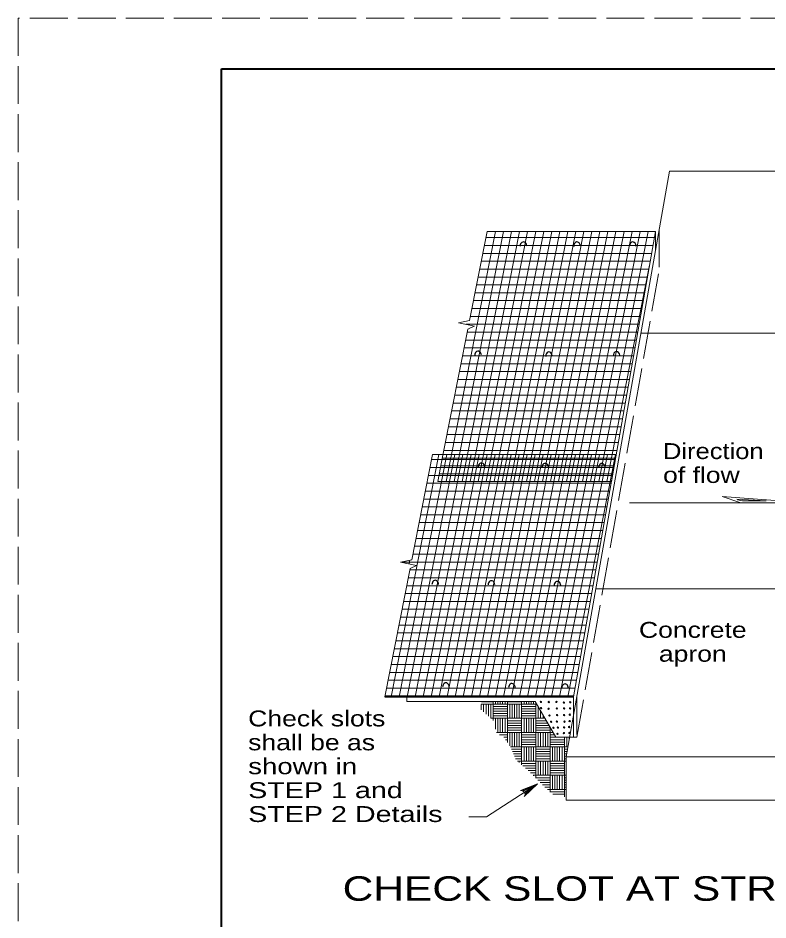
# Model space of a CAD drawing. Extents: x 1083.1 to 1117.1, y 719.4 to 741.4.
# Drawn here: x 1083.13 to 1090.49, y 732.5 to 741.35 of the extents above; entities that cross this region are included whole.
import ezdxf
from ezdxf.enums import TextEntityAlignment as Align

# ---------------------------------------------------------------- set-up
doc = ezdxf.new("R2010")
doc.units = 0
doc.header["$LTSCALE"] = 0.062
doc.linetypes.add('LONG_DASHED', pattern=[7.5, 6, -1.5])
doc.layers.add('1', color=7, linetype='Continuous', lineweight=13)

msp = doc.modelspace()

# ---------------------------------------------------------------- linework, layer by layer
at = {"layer": '1', "lineweight": 25}
msp.add_line((1085.12642, 740.85408), (1116.62642, 740.85408), dxfattribs=at)
at = {"layer": '1'}
for p, q in [((1088.51183, 734.09967), (1089.52617, 739.8515)), ((1093.0215, 739.8515), (1089.52617, 739.8515)), ((1087.33167, 736.80383), (1087.81692, 739.259)), ((1087.41058, 736.80383), (1087.89583, 739.259)), ((1087.48942, 736.80383), (1087.97467, 739.259)), ((1087.56825, 736.80383), (1088.0535, 739.259)), ((1087.64708, 736.80383), (1088.13242, 739.259)), ((1087.72342, 739.19792), (1089.37667, 739.19792)), ((1087.726, 736.80383), (1088.21125, 739.259)), ((1087.7355, 739.259), (1089.38733, 739.259)), ((1087.80483, 736.80383), (1088.29017, 739.259)), ((1087.88375, 736.80383), (1088.369, 739.259)), ((1087.96267, 736.80383), (1088.44792, 739.259)), ((1088.0415, 736.80383), (1088.52675, 739.259)), ((1088.12042, 736.80383), (1088.60567, 739.259)), ((1088.19925, 736.80383), (1088.6845, 739.259)), ((1088.27817, 736.80383), (1088.76342, 739.259)), ((1088.357, 736.80383), (1088.84233, 739.259)), ((1088.43592, 736.80383), (1088.92117, 739.259)), ((1088.51475, 736.80383), (1089.00008, 739.259)), ((1088.59367, 736.80383), (1089.07892, 739.259)), ((1088.67258, 736.80383), (1089.15783, 739.259)), ((1088.75142, 736.80383), (1089.23667, 739.259)), ((1088.83033, 736.80383), (1089.31558, 739.259)), ((1089.38733, 739.259), (1088.9545, 736.80383)), ((1089.38733, 739.259), (1089.38733, 739.06475)), ((1087.70817, 739.1205), (1089.363, 739.1205)), ((1087.69283, 739.04317), (1089.34933, 739.04317)), ((1087.6775, 738.96583), (1089.33567, 738.96583)), ((1088.90917, 736.80383), (1089.32892, 738.92725)), ((1087.66225, 738.88842), (1089.32208, 738.88842)), ((1087.63158, 738.73367), (1089.29475, 738.73367)), ((1087.64692, 738.81108), (1089.30842, 738.81108)), ((1087.61633, 738.65633), (1089.28108, 738.65633)), ((1087.60108, 738.57892), (1089.26742, 738.57892)), ((1087.58583, 738.50158), (1089.25383, 738.50158)), ((1087.5705, 738.42417), (1089.24017, 738.42417)), ((1087.30092, 737.06058), (1087.54575, 738.29875)), ((1087.52417, 738.34683), (1089.2265, 738.34683)), ((1087.54575, 738.29875), (1087.60658, 738.32825)), ((1087.53992, 738.26942), (1089.21283, 738.26942)), ((1092.74075, 738.25933), (1089.24533, 738.25933)), ((1087.50933, 738.11467), (1089.18567, 738.11467)), ((1087.52458, 738.19208), (1089.19933, 738.19208)), ((1087.494, 738.03733), (1089.172, 738.03733)), ((1087.47867, 737.95992), (1089.15833, 737.95992)), ((1087.46342, 737.88258), (1089.14467, 737.88258)), ((1087.44808, 737.80525), (1089.13108, 737.80525)), ((1087.43275, 737.72783), (1089.11742, 737.72783)), ((1087.41758, 737.6505), (1089.10375, 737.6505)), ((1087.387, 737.49575), (1089.07642, 737.49575)), ((1087.40225, 737.57308), (1089.09008, 737.57308)), ((1087.37167, 737.41833), (1089.06283, 737.41833)), ((1087.35633, 737.341), (1089.04917, 737.341)), ((1087.34108, 737.26358), (1089.0355, 737.26358)), ((1087.32575, 737.18625), (1089.02192, 737.18625)), ((1086.7905, 734.6895), (1087.26042, 737.06717)), ((1086.86942, 734.6895), (1087.33933, 737.06717)), ((1086.94825, 734.6895), (1087.41825, 737.06717)), ((1087.02717, 734.6895), (1087.49708, 737.06717)), ((1087.106, 734.6895), (1087.576, 737.06717)), ((1087.18492, 734.6895), (1087.65483, 737.06717)), ((1087.25025, 736.80383), (1087.30092, 737.06058)), ((1087.26375, 734.6895), (1087.73375, 737.06717)), ((1087.3105, 737.10883), (1089.00825, 737.10883)), ((1087.34267, 734.6895), (1087.81258, 737.06717)), ((1087.42158, 734.6895), (1087.8915, 737.06717)), ((1087.50042, 734.6895), (1087.97033, 737.06717)), ((1087.57933, 734.6895), (1088.04925, 737.06717)), ((1087.65817, 734.6895), (1088.12817, 737.06717)), ((1087.73708, 734.6895), (1088.207, 737.06717)), ((1087.81592, 734.6895), (1088.28592, 737.06717)), ((1087.89483, 734.6895), (1088.36475, 737.06717)), ((1087.97367, 734.6895), (1088.44367, 737.06717)), ((1088.05258, 734.6895), (1088.5225, 737.06717)), ((1088.1315, 734.6895), (1088.60142, 737.06717)), ((1088.21033, 734.6895), (1088.68025, 737.06717)), ((1088.28925, 734.6895), (1088.75917, 737.06717)), ((1088.36808, 734.6895), (1088.83808, 737.06717)), ((1088.44692, 734.6895), (1088.91692, 737.06717)), ((1088.52575, 734.6895), (1088.99583, 737.06717)), ((1089.00092, 737.06717), (1088.58167, 734.6895)), ((1087.18892, 737.018), (1088.99225, 737.018)), ((1087.29517, 737.0315), (1088.99467, 737.0315)), ((1087.17367, 736.94067), (1088.97858, 736.94067)), ((1087.26517, 736.87975), (1088.96467, 736.87975)), ((1087.28017, 736.95558), (1088.97967, 736.95558)), ((1087.143, 736.78592), (1088.95133, 736.78592)), ((1087.15833, 736.86325), (1088.96492, 736.86325)), ((1087.25025, 736.80383), (1088.9545, 736.80383)), ((1087.12775, 736.7085), (1088.93767, 736.7085)), ((1087.11242, 736.63117), (1088.924, 736.63117)), ((1087.09717, 736.55375), (1088.91033, 736.55375)), ((1087.08183, 736.47642), (1088.89675, 736.47642)), ((1087.06658, 736.399), (1088.88308, 736.399)), ((1087.05133, 736.32167), (1088.86942, 736.32167)), ((1087.02067, 736.16692), (1088.84217, 736.16692)), ((1087.036, 736.24425), (1088.85575, 736.24425)), ((1087.00542, 736.0895), (1088.82858, 736.0895)), ((1086.888, 736.01217), (1088.81492, 736.01217)), ((1086.89367, 736.00942), (1086.8945, 736.0135)), ((1086.96925, 735.99292), (1086.97675, 736.03075)), ((1086.72858, 734.6895), (1086.97733, 735.94775)), ((1086.97475, 735.93475), (1088.80125, 735.93475)), ((1086.9595, 735.85742), (1088.78758, 735.85742)), ((1086.94417, 735.78008), (1088.77392, 735.78008)), ((1092.29817, 735.74967), (1088.80283, 735.74967)), ((1086.92883, 735.70267), (1088.76033, 735.70267)), ((1086.89833, 735.54792), (1088.733, 735.54792)), ((1086.91358, 735.62533), (1088.74667, 735.62533)), ((1086.88308, 735.47058), (1088.71933, 735.47058)), ((1086.86775, 735.39317), (1088.70575, 735.39317)), ((1086.85242, 735.31583), (1088.69208, 735.31583)), ((1086.83717, 735.23842), (1088.67842, 735.23842)), ((1086.82183, 735.16108), (1088.66483, 735.16108)), ((1086.8065, 735.08367), (1088.65117, 735.08367)), ((1086.77592, 734.92892), (1088.62392, 734.92892)), ((1086.79125, 735.00633), (1088.63758, 735.00633)), ((1086.76067, 734.85158), (1088.61025, 734.85158)), ((1086.74533, 734.77425), (1088.59658, 734.77425)), ((1086.73, 734.69683), (1088.583, 734.69683)), ((1086.94475, 734.6895), (1086.94475, 734.64275)), ((1088.58167, 734.6895), (1088.58167, 734.4955)), ((1088.20683, 734.64275), (1086.94475, 734.64275)), ((1087.67692, 734.56183), (1087.67692, 734.61242)), ((1088.22142, 734.61758), (1087.67742, 734.61758)), ((1087.7935, 734.64083), (1087.67975, 734.64083)), ((1087.70025, 734.54758), (1087.70025, 734.61758)), ((1087.72358, 734.54758), (1087.72358, 734.61758)), ((1087.74692, 734.54758), (1087.74692, 734.61758)), ((1087.77025, 734.54758), (1087.77025, 734.61758)), ((1087.7935, 734.45683), (1087.7935, 734.64275)), ((1087.8635, 734.59425), (1087.7935, 734.59425)), ((1087.8635, 734.57092), (1087.7935, 734.57092)), ((1087.81683, 734.61758), (1087.81683, 734.64275)), ((1087.84017, 734.61758), (1087.84017, 734.64275)), ((1087.8635, 734.61758), (1087.8635, 734.64275)), ((1087.9335, 734.59425), (1087.8635, 734.59425)), ((1087.9335, 734.57092), (1087.8635, 734.57092)), ((1087.88683, 734.61758), (1087.88683, 734.64275)), ((1087.91017, 734.61758), (1087.91017, 734.64275)), ((1087.9335, 734.24017), (1087.9335, 734.64275)), ((1088.07342, 734.64083), (1087.9335, 734.64083)), ((1087.95683, 734.54758), (1087.95683, 734.61758)), ((1087.98008, 734.54758), (1087.98008, 734.61758)), ((1088.00342, 734.54758), (1088.00342, 734.61758)), ((1088.02675, 734.54758), (1088.02675, 734.61758)), ((1088.05008, 734.54758), (1088.05008, 734.61758)), ((1088.07342, 734.02175), (1088.07342, 734.64275)), ((1088.14342, 734.59425), (1088.07342, 734.59425)), ((1088.14342, 734.57092), (1088.07342, 734.57092)), ((1088.09675, 734.61758), (1088.09675, 734.64275)), ((1088.12008, 734.61758), (1088.12008, 734.64275)), ((1088.14342, 734.61758), (1088.14342, 734.64275)), ((1088.21333, 734.59425), (1088.14342, 734.59425)), ((1088.21333, 734.57092), (1088.14342, 734.57092)), ((1088.16667, 734.61758), (1088.16667, 734.64275)), ((1088.19, 734.61758), (1088.19, 734.64275)), ((1088.40858, 734.29375), (1088.20683, 734.64275)), ((1088.21333, 733.89075), (1088.21333, 734.63158)), ((1088.23667, 734.54758), (1088.23667, 734.59125)), ((1087.70025, 734.54083), (1087.70025, 734.54758)), ((1087.72358, 734.51983), (1087.72358, 734.54758)), ((1087.74692, 734.49883), (1087.74692, 734.54758)), ((1087.77025, 734.47783), (1087.77025, 734.54758)), ((1088.30233, 734.47767), (1087.7705, 734.47767)), ((1087.8635, 734.54758), (1087.7935, 734.54758)), ((1087.8635, 734.52425), (1087.7935, 734.52425)), ((1087.8635, 734.50092), (1087.7935, 734.50092)), ((1087.81683, 734.37233), (1087.81683, 734.47767)), ((1087.84017, 734.33775), (1087.84017, 734.47767)), ((1087.9335, 734.54758), (1087.8635, 734.54758)), ((1087.9335, 734.52425), (1087.8635, 734.52425)), ((1087.9335, 734.50092), (1087.8635, 734.50092)), ((1087.8635, 734.33775), (1087.8635, 734.47767)), ((1087.88683, 734.33775), (1087.88683, 734.47767)), ((1087.91017, 734.33775), (1087.91017, 734.47767)), ((1087.95683, 734.47767), (1087.95683, 734.54758)), ((1087.98008, 734.47767), (1087.98008, 734.54758)), ((1088.00342, 734.47767), (1088.00342, 734.54758)), ((1088.02675, 734.47767), (1088.02675, 734.54758)), ((1088.05008, 734.47767), (1088.05008, 734.54758)), ((1088.14342, 734.54758), (1088.07342, 734.54758)), ((1088.14342, 734.52425), (1088.07342, 734.52425)), ((1088.14342, 734.50092), (1088.07342, 734.50092)), ((1088.09675, 734.33775), (1088.09675, 734.47767)), ((1088.12008, 734.33775), (1088.12008, 734.47767)), ((1088.21333, 734.54758), (1088.14342, 734.54758)), ((1088.21333, 734.52425), (1088.14342, 734.52425)), ((1088.21333, 734.50092), (1088.14342, 734.50092)), ((1088.14342, 734.33775), (1088.14342, 734.47767)), ((1088.16667, 734.33775), (1088.16667, 734.47767)), ((1088.19, 734.33775), (1088.19, 734.47767)), ((1088.23667, 734.47767), (1088.23667, 734.54758)), ((1088.26, 734.47767), (1088.26, 734.55083)), ((1088.26, 734.54758), (1088.26, 734.55083)), ((1088.28333, 734.47767), (1088.28333, 734.5105)), ((1088.07342, 734.45433), (1087.9335, 734.45433)), ((1088.07342, 734.431), (1087.9335, 734.431)), ((1088.07342, 734.40767), (1087.9335, 734.40767)), ((1088.31583, 734.45433), (1088.21333, 734.45433)), ((1088.32925, 734.431), (1088.21333, 734.431)), ((1088.34267, 734.40767), (1088.21333, 734.40767)), ((1088.35325, 733.75117), (1088.35325, 734.38942)), ((1088.38317, 734.33775), (1087.82483, 734.33775)), ((1087.8635, 734.31442), (1087.85642, 734.31442)), ((1087.9335, 734.31442), (1087.8635, 734.31442)), ((1088.07342, 734.38433), (1087.9335, 734.38433)), ((1088.07342, 734.361), (1087.9335, 734.361)), ((1087.95683, 734.26775), (1087.95683, 734.33775)), ((1087.98008, 734.26775), (1087.98008, 734.33775)), ((1088.00342, 734.26775), (1088.00342, 734.33775)), ((1088.02675, 734.26775), (1088.02675, 734.33775)), ((1088.05008, 734.26775), (1088.05008, 734.33775)), ((1088.14342, 734.31442), (1088.07342, 734.31442)), ((1088.21333, 734.31442), (1088.14342, 734.31442)), ((1088.35325, 734.38433), (1088.21333, 734.38433)), ((1088.35325, 734.361), (1088.21333, 734.361)), ((1088.23667, 734.26775), (1088.23667, 734.33775)), ((1088.26, 734.26775), (1088.26, 734.33775)), ((1088.28333, 734.26775), (1088.28333, 734.33775)), ((1088.30667, 734.26775), (1088.30667, 734.33775)), ((1088.32992, 734.26775), (1088.32992, 734.33775)), ((1088.39667, 734.31442), (1088.35325, 734.31442)), ((1088.37658, 734.33775), (1088.37658, 734.349)), ((1087.9335, 734.29108), (1087.89842, 734.29108)), ((1087.9335, 734.26775), (1087.9145, 734.26775)), ((1087.9335, 734.24442), (1087.93058, 734.24442)), ((1087.95683, 734.20625), (1087.95683, 734.26775)), ((1087.98008, 734.19775), (1087.98008, 734.26775)), ((1088.00342, 734.19775), (1088.00342, 734.26775)), ((1088.02675, 734.19775), (1088.02675, 734.26775)), ((1088.05008, 734.19775), (1088.05008, 734.26775)), ((1088.14342, 734.29108), (1088.07342, 734.29108)), ((1088.14342, 734.26775), (1088.07342, 734.26775)), ((1088.14342, 734.24442), (1088.07342, 734.24442)), ((1088.14342, 734.22108), (1088.07342, 734.22108)), ((1088.21333, 734.29108), (1088.14342, 734.29108)), ((1088.21333, 734.26775), (1088.14342, 734.26775)), ((1088.21333, 734.24442), (1088.14342, 734.24442)), ((1088.21333, 734.22108), (1088.14342, 734.22108)), ((1088.23667, 734.19775), (1088.23667, 734.26775)), ((1088.26, 734.19775), (1088.26, 734.26775)), ((1088.28333, 734.19775), (1088.28333, 734.26775)), ((1088.30667, 734.19775), (1088.30667, 734.26775)), ((1088.32992, 734.19775), (1088.32992, 734.26775)), ((1088.42325, 734.29108), (1088.35325, 734.29108)), ((1088.42325, 734.26775), (1088.35325, 734.26775)), ((1088.42325, 734.24442), (1088.35325, 734.24442)), ((1088.42325, 734.22108), (1088.35325, 734.22108)), ((1088.40858, 734.29375), (1088.54608, 734.29375)), ((1088.49325, 734.29108), (1088.42325, 734.29108)), ((1088.49325, 734.26775), (1088.42325, 734.26775)), ((1088.49325, 734.24442), (1088.42325, 734.24442)), ((1088.49325, 734.22108), (1088.42325, 734.22108)), ((1088.49325, 733.70808), (1088.49325, 734.29375)), ((1088.5165, 734.26775), (1088.5165, 734.29375)), ((1088.5165, 734.19775), (1088.5165, 734.26775)), ((1088.53983, 734.25842), (1088.53983, 734.29375)), ((1088.52917, 734.19775), (1087.96267, 734.19775)), ((1088.07342, 734.1745), (1087.973, 734.1745)), ((1088.07342, 734.15117), (1087.98333, 734.15117)), ((1088.07342, 734.12783), (1087.99367, 734.12783)), ((1088.09675, 734.05783), (1088.09675, 734.19775)), ((1088.12008, 734.05783), (1088.12008, 734.19775)), ((1088.14342, 734.05783), (1088.14342, 734.19775)), ((1088.16667, 734.05783), (1088.16667, 734.19775)), ((1088.19, 734.05783), (1088.19, 734.19775)), ((1088.35325, 734.1745), (1088.21333, 734.1745)), ((1088.35325, 734.15117), (1088.21333, 734.15117)), ((1088.35325, 734.12783), (1088.21333, 734.12783)), ((1088.37658, 734.05783), (1088.37658, 734.19775)), ((1088.39992, 734.05783), (1088.39992, 734.19775)), ((1088.42325, 734.05783), (1088.42325, 734.19775)), ((1088.44658, 734.05783), (1088.44658, 734.19775)), ((1088.46992, 734.05783), (1088.46992, 734.19775)), ((1088.525, 734.1745), (1088.49325, 734.1745)), ((1088.52092, 734.15117), (1088.49325, 734.15117)), ((1088.51683, 734.12783), (1088.49325, 734.12783)), ((1088.07342, 734.1045), (1088.004, 734.1045)), ((1088.07342, 734.08117), (1088.01433, 734.08117)), ((1088.51183, 734.05783), (1088.03375, 734.05783)), ((1088.05008, 734.043), (1088.05008, 734.05783)), ((1088.14342, 734.03458), (1088.07342, 734.03458)), ((1088.21333, 734.03458), (1088.14342, 734.03458)), ((1088.35325, 734.1045), (1088.21333, 734.1045)), ((1088.35325, 734.08117), (1088.21333, 734.08117)), ((1088.23667, 733.98792), (1088.23667, 734.05783)), ((1088.26, 733.98792), (1088.26, 734.05783)), ((1088.28333, 733.98792), (1088.28333, 734.05783)), ((1088.30667, 733.98792), (1088.30667, 734.05783)), ((1088.32992, 733.98792), (1088.32992, 734.05783)), ((1088.42325, 734.03458), (1088.35325, 734.03458)), ((1088.49325, 734.03458), (1088.42325, 734.03458)), ((1088.51267, 734.1045), (1088.49325, 734.1045)), ((1088.51183, 734.08117), (1088.49325, 734.08117)), ((1088.51183, 733.67267), (1088.51183, 734.09967)), ((1092.00725, 734.09967), (1088.51183, 734.09967)), ((1088.14342, 734.01125), (1088.08492, 734.01125)), ((1088.14342, 733.98792), (1088.1105, 733.98792)), ((1088.14342, 733.96458), (1088.13608, 733.96458)), ((1088.21333, 734.01125), (1088.14342, 734.01125)), ((1088.21333, 733.98792), (1088.14342, 733.98792)), ((1088.21333, 733.96458), (1088.14342, 733.96458)), ((1088.23667, 733.91792), (1088.23667, 733.98792)), ((1088.26, 733.91792), (1088.26, 733.98792)), ((1088.28333, 733.91792), (1088.28333, 733.98792)), ((1088.30667, 733.91792), (1088.30667, 733.98792)), ((1088.32992, 733.91792), (1088.32992, 733.98792)), ((1088.42325, 734.01125), (1088.35325, 734.01125)), ((1088.42325, 733.98792), (1088.35325, 733.98792)), ((1088.42325, 733.96458), (1088.35325, 733.96458)), ((1088.49325, 734.01125), (1088.42325, 734.01125)), ((1088.49325, 733.98792), (1088.42325, 733.98792)), ((1088.49325, 733.96458), (1088.42325, 733.96458)), ((1088.21333, 733.94125), (1088.16158, 733.94125)), ((1088.51183, 733.91792), (1088.18617, 733.91792)), ((1088.19, 733.91408), (1088.19, 733.91792)), ((1088.35325, 733.89467), (1088.21333, 733.89467)), ((1088.35325, 733.87133), (1088.23275, 733.87133)), ((1088.42325, 733.94125), (1088.35325, 733.94125)), ((1088.37658, 733.778), (1088.37658, 733.91792)), ((1088.39992, 733.778), (1088.39992, 733.91792)), ((1088.49325, 733.94125), (1088.42325, 733.94125)), ((1088.42325, 733.778), (1088.42325, 733.91792)), ((1088.44658, 733.778), (1088.44658, 733.91792)), ((1088.46992, 733.778), (1088.46992, 733.91792)), ((1088.51183, 733.89467), (1088.49325, 733.89467)), ((1088.51183, 733.87133), (1088.49325, 733.87133)), ((1088.079, 733.76683), (1088.22783, 733.83567)), ((1088.08983, 733.76158), (1088.22783, 733.83567)), ((1088.10017, 733.75108), (1088.22783, 733.83567)), ((1088.105, 733.74075), (1088.22783, 733.83567)), ((1088.10658, 733.7285), (1088.22783, 733.83567)), ((1088.35325, 733.848), (1088.256, 733.848)), ((1088.35325, 733.82467), (1088.27933, 733.82467)), ((1088.35325, 733.80133), (1088.30258, 733.80133)), ((1088.51183, 733.778), (1088.326, 733.778)), ((1088.32992, 733.77408), (1088.32992, 733.778)), ((1088.51183, 733.848), (1088.49325, 733.848)), ((1088.51183, 733.82467), (1088.49325, 733.82467)), ((1088.51183, 733.80133), (1088.49325, 733.80133)), ((1088.42325, 733.75475), (1088.35325, 733.75475)), ((1088.42325, 733.73142), (1088.37942, 733.73142)), ((1088.49325, 733.75475), (1088.42325, 733.75475)), ((1088.49325, 733.73142), (1088.42325, 733.73142)), ((1092.00725, 733.67267), (1088.51183, 733.67267))]:
    msp.add_line(p, q, dxfattribs=at)
at = {"layer": '1', "linetype": 'LONG_DASHED'}
for p, q in [((1089.42542, 739.28042), (1089.42542, 738.88475)), ((1088.61592, 734.29375), (1089.42917, 738.90583)), ((1088.61592, 734.6895), (1088.61592, 734.29375)), ((1088.58167, 734.49533), (1088.58167, 734.29375)), ((1088.61592, 734.29375), (1088.54608, 734.29375))]:
    msp.add_line(p, q, dxfattribs=at)
at = {"layer": '1', "lineweight": 35}
msp.add_line((1088.58167, 734.6895), (1086.72858, 734.6895), dxfattribs=at)
at = {"layer": '1', "linetype": 'LONG_DASHED'}
msp.add_lwpolyline([(1083.12642, 719.35408), (1117.12642, 719.35408), (1117.12642, 741.35408), (1083.12642, 741.35408)], close=True, dxfattribs=at)
at = {"layer": '1', "lineweight": 25}
msp.add_lwpolyline([(1116.62642, 719.85408), (1085.12642, 719.85408), (1085.12642, 740.85408)], dxfattribs=at)
at = {"layer": '1', "lineweight": 40}
msp.add_lwpolyline([(1085.12642, 740.85408), (1116.62642, 740.85408), (1116.62642, 719.85408), (1085.12642, 719.85408)], close=True, dxfattribs=at)
msp.add_lwpolyline([(1085.12642, 740.85408), (1116.62642, 740.85408), (1116.62642, 719.85408), (1085.12642, 719.85408)], close=True, dxfattribs=at)
at = {"layer": '1'}
for points in [[(1087.60925, 738.32825), (1087.45275, 738.36242), (1087.56283, 738.38542), (1087.7355, 739.259)], [(1086.9945, 736.03442), (1087.19867, 737.06717), (1089.00092, 737.06717)], [(1089.13208, 736.59283), (1090.86817, 736.59283), (1090.04475, 736.65542), (1090.216, 736.59542)], [(1090.18867, 736.62933), (1090.47633, 736.61367), (1090.24317, 736.61367), (1090.19358, 736.62408)], [(1086.97725, 735.94775), (1087.039, 735.97767), (1086.88442, 736.01142), (1086.99442, 736.03442)], [(1088.22783, 733.83567), (1087.72892, 733.5095), (1087.55508, 733.5095)], [(1088.06075, 733.7675), (1088.22783, 733.83567), (1088.09983, 733.70842)]]:
    msp.add_lwpolyline(points, dxfattribs=at)
msp.add_arc((1088.06838, 733.73004), 0.0382, 325.58794, 101.41407, dxfattribs=at)
at = {"layer": '1', "lineweight": 25}
for centre, major_axis, ratio, start_param, end_param in [((1088.09124, 739.11485), (0.00067, 0.04098), 0.78812, 4.7123961, 7.8539888), ((1088.61815, 739.11558), (-0.00492, 0.04069), 0.788117, 4.7123369, 7.8539295), ((1089.16443, 739.11426), (0.00173, 0.04095), 0.788119, 4.7124075, 7.8540001), ((1087.64644, 738.04237), (-0.00492, 0.04069), 0.788117, 4.7123369, 7.8539295), ((1088.3422, 738.03454), (-0.00492, 0.04069), 0.788117, 4.7123369, 7.8539295), ((1089.0068, 738.03845), (-0.00492, 0.04069), 0.788117, 4.7123369, 7.8539295), ((1087.6781, 736.9436), (0.00067, 0.04098), 0.78812, 4.7123961, 7.8539888), ((1088.30472, 736.93985), (0.00067, 0.04098), 0.78812, 4.7123961, 7.8539888), ((1088.86163, 736.93877), (0.00067, 0.04098), 0.78812, 4.7123961, 7.8539888), ((1087.22407, 735.79159), (0.00067, 0.04098), 0.78812, 4.7123961, 7.8539888), ((1087.77639, 735.78818), (0.00067, 0.04098), 0.78812, 4.7123961, 7.8539888), ((1088.42475, 735.78127), (0.00067, 0.04098), 0.78812, 4.7123961, 7.8539888), ((1087.32935, 734.78501), (0.00067, 0.04098), 0.78812, 4.7123961, 7.8539888), ((1087.9773, 734.77809), (0.00067, 0.04098), 0.78812, 4.7123961, 7.8539888), ((1088.50022, 734.77468), (0.00067, 0.04098), 0.78812, 4.7123961, 7.8539888)]:
    msp.add_ellipse(centre, major_axis=major_axis, ratio=ratio, start_param=start_param, end_param=end_param, dxfattribs=at)
at = {"layer": '1'}
for centre in [(1088.26332, 734.63837), (1088.26498, 734.57757), (1088.33828, 734.57158), (1088.34028, 734.6377), (1088.41458, 734.6387), (1088.41908, 734.57482), (1088.48838, 734.63221), (1088.49013, 734.57432), (1088.54993, 734.57449), (1088.55152, 734.63496), (1088.34678, 734.5052), (1088.42108, 734.50895), (1088.49096, 734.50895), (1088.54568, 734.51336), (1088.36219, 734.44382), (1088.38509, 734.38535), (1088.42016, 734.44548), (1088.42999, 734.38635), (1088.49096, 734.38835), (1088.49438, 734.44473), (1088.53927, 734.39218), (1088.54535, 734.45031), (1088.42449, 734.32522), (1088.48921, 734.33205), (1088.5421, 734.3338)]:
    msp.add_ellipse(centre, major_axis=(0.00673, 0), ratio=0.999895, dxfattribs=at)

# ---------------------------------------------------------------- texts
for s, height, width, p in [('Direction', 0.156, 1.2, (1089.46217, 737.0235)), ('of flow', 0.156, 1.25, (1089.46217, 736.78883)), ('Check slots', 0.156, 1.25, (1085.387, 734.39817)), ('shall be as', 0.156, 1.25, (1085.387, 734.1635)), ('shown in', 0.156, 1.3, (1085.387, 733.92883)), ('STEP 1 and', 0.156, 1.35, (1085.387, 733.69417)), ('STEP 2 Details', 0.156, 1.35, (1085.387, 733.4595)), ('CHECK SLOT AT STRUCTURES', 0.24, 1.3, (1086.31508, 732.68608))]:
    msp.add_text(s, height=height, dxfattribs=dict(at, width=width)).set_placement(p)
at = {"layer": '1', "width": 1.25}
for s, p in [('Concrete', (1089.75471, 735.268)), ('apron', (1089.75471, 735.03333))]:
    msp.add_text(s, height=0.156, dxfattribs=at).set_placement(p, align=Align.CENTER)

doc.saveas('drawing.dxf')
